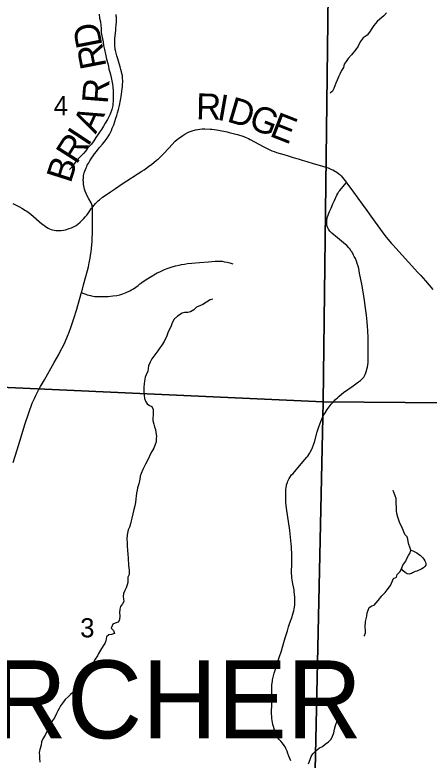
# Model space of a CAD drawing. Extents: x 0 to 34, y 0 to 22.
# Drawn here: x 14.795 to 15.701, y 15.132 to 16.764 of the extents above; entities that cross this region are included whole.
import ezdxf

# ---------------------------------------------------------------- set-up
doc = ezdxf.new("R2010")
doc.units = 0
for name, color, linetype in [('GM_X_Corporation', 7, 'Continuous'), ('GM_X_County_Road', 7, 'Continuous'), ('GM_X_County_Road_Text', 7, 'Continuous'), ('GM_X_Minor_River', 7, 'Continuous'), ('GM_X_Section_Text', 7, 'Continuous'), ('GM_X_Township_Road', 7, 'Continuous'), ('GM_X_Township_Text', 7, 'Continuous')]:
    doc.layers.add(name, color=color, linetype=linetype)

msp = doc.modelspace()

# ---------------------------------------------------------------- linework, layer by layer
at = {"layer": 'GM_X_Corporation'}
for points in [[(14.4709, 16.9847), (15.4816, 16.9282), (15.4691, 15.9163), (14.4583, 15.9623)], [(15.4816, 16.9282), (16.466, 16.9214), (16.4563, 15.9084), (15.4691, 15.9163)], [(14.4583, 15.9623), (15.4691, 15.9163), (15.4475, 14.9085), (14.443, 14.9501)], [(15.4691, 15.9163), (16.4563, 15.9084), (16.441, 14.8856), (15.4475, 14.9085)]]:
    msp.add_lwpolyline(points, close=True, dxfattribs=at)
at = {"layer": 'GM_X_County_Road'}
for points in [[(14.9643, 16.3423), (14.964, 16.3442), (14.9635, 16.3464), (14.9629, 16.3487), (14.9622, 16.3506), (14.9615, 16.3522), (14.9565, 16.361), (14.9523, 16.3687), (14.9504, 16.3728), (14.9484, 16.3776), (14.9468, 16.3825), (14.9461, 16.3855), (14.9454, 16.3896), (14.9449, 16.393), (14.9447, 16.3954), (14.9446, 16.3986), (14.9445, 16.401), (14.9446, 16.4074), (14.9451, 16.4116), (14.9457, 16.4148), (14.9465, 16.418), (14.9478, 16.4218), (14.949, 16.4252), (14.9505, 16.4288), (14.9519, 16.4318), (14.9532, 16.4344), (14.9546, 16.4368), (14.9563, 16.4399), (14.9587, 16.4439), (14.9627, 16.4501), (14.966, 16.4548), (14.9691, 16.4592), (14.973, 16.4645), (14.9769, 16.4695), (14.9808, 16.4743), (14.9862, 16.4804), (14.9925, 16.4883), (14.9964, 16.4937), (15, 16.4993), (15.0016, 16.5019), (15.0033, 16.5048), (15.0047, 16.5078), (15.006, 16.5106), (15.008, 16.5154), (15.011, 16.5229), (15.0134, 16.5301), (15.0158, 16.5379), (15.0177, 16.5437), (15.0192, 16.5491), (15.0213, 16.5568), (15.0235, 16.565), (15.0245, 16.569), (15.0255, 16.5737), (15.0267, 16.5803), (15.0274, 16.5848), (15.0281, 16.5899), (15.0289, 16.5961), (15.0295, 16.6015), (15.03, 16.6067), (15.0303, 16.6098), (15.0305, 16.6126), (15.0307, 16.6159), (15.0308, 16.6195), (15.0305, 16.6249), (15.0302, 16.628), (15.0299, 16.6305), (15.029, 16.6354), (15.0281, 16.6393), (15.0269, 16.6441), (15.0253, 16.6498), (15.0201, 16.6673), (15.0179, 16.6743), (15.0154, 16.6827), (15.0148, 16.6857), (15.0143, 16.688), (15.014, 16.6903), (15.0135, 16.695), (15.0133, 16.6977), (15.0132, 16.7), (15.0132, 16.7028), (15.0133, 16.7069), (15.0136, 16.7117), (15.0154, 16.7301), (15.0158, 16.7349), (15.0163, 16.7422), (15.0168, 16.7483), (15.017, 16.7537), (15.017, 16.7577), (15.0169, 16.7593), (15.0167, 16.7605), (15.0166, 16.7617), (15.0161, 16.7642)], [(14.9643, 16.3423), (14.9654, 16.3437), (14.9685, 16.3474), (14.9712, 16.3504), (14.9771, 16.3563), (14.9798, 16.3589), (14.9865, 16.3644), (14.9899, 16.367), (15.0037, 16.3765), (15.0147, 16.3838), (15.0296, 16.3936), (15.0726, 16.4214), (15.0776, 16.4247), (15.09, 16.4336), (15.0939, 16.4365), (15.105, 16.4456), (15.1089, 16.4489), (15.1142, 16.4538), (15.1202, 16.4597), (15.1319, 16.4719), (15.1458, 16.487), (15.1496, 16.4907), (15.1537, 16.4939), (15.1569, 16.4962), (15.1621, 16.4998), (15.1665, 16.5024), (15.1716, 16.5052), (15.1765, 16.5075), (15.1828, 16.5099), (15.1898, 16.5118), (15.1949, 16.5129), (15.1992, 16.5135), (15.2045, 16.5139), (15.2107, 16.5141), (15.2222, 16.5137), (15.226, 16.5133), (15.2359, 16.5119), (15.2407, 16.5111), (15.2592, 16.5075), (15.2639, 16.5064), (15.2783, 16.5027), (15.2821, 16.5016), (15.2957, 16.4973), (15.299, 16.496), (15.3061, 16.4929), (15.3096, 16.4912), (15.3188, 16.486), (15.3379, 16.4753), (15.3423, 16.473), (15.3541, 16.4675), (15.3573, 16.4662), (15.362, 16.4645), (15.3674, 16.4627), (15.3835, 16.4577), (15.3926, 16.4549), (15.4041, 16.4514), (15.4092, 16.4499), (15.415, 16.4482), (15.4235, 16.4457), (15.434, 16.4427), (15.4479, 16.4387), (15.4657, 16.4334), (15.4773, 16.4297), (15.4804, 16.4286), (15.488, 16.4255), (15.4907, 16.4242), (15.4965, 16.4209), (15.499, 16.4193), (15.5041, 16.4154), (15.5057, 16.4139), (15.5086, 16.4111), (15.5115, 16.4079), (15.5178, 16.4003), (15.5202, 16.3971), (15.5214, 16.3954), (15.5355, 16.3755), (15.5452, 16.3623), (15.5549, 16.3492), (15.5649, 16.3353), (15.574, 16.3228), (15.6045, 16.281), (15.6076, 16.277), (15.6191, 16.263), (15.6217, 16.2601), (15.6768, 16.1999), (15.6831, 16.1928), (15.6934, 16.1811), (15.7011, 16.1723), (15.7095, 16.1624)], [(14.7901, 16.3504), (14.8045, 16.3432), (14.8096, 16.3405), (14.8181, 16.3357), (14.8208, 16.334), (14.8264, 16.3299), (14.8295, 16.3274), (14.8537, 16.3066), (14.857, 16.304), (14.8607, 16.3012), (14.8641, 16.2989), (14.8676, 16.2969), (14.8707, 16.2954), (14.8738, 16.2942), (14.8767, 16.2932), (14.8804, 16.2923), (14.8843, 16.2917), (14.8878, 16.2914), (14.892, 16.2913), (14.8959, 16.2916), (14.9008, 16.2922), (14.9056, 16.2934), (14.9135, 16.2957), (14.9183, 16.2974), (14.9218, 16.2989), (14.9256, 16.3008), (14.9286, 16.3027), (14.9325, 16.3057), (14.9375, 16.3099), (14.9401, 16.3123), (14.9458, 16.3181), (14.9489, 16.3216), (14.9519, 16.3252), (14.9557, 16.3304), (14.9626, 16.3402), (14.9643, 16.3423)]]:
    msp.add_lwpolyline(points, dxfattribs=at)
at = {"layer": 'GM_X_Minor_River'}
for points in [[(14.979, 16.7655), (14.9802, 16.7568), (14.9819, 16.7484), (14.9828, 16.7412), (14.9833, 16.734), (14.9838, 16.7249), (14.9847, 16.7181), (14.9863, 16.7113), (14.9876, 16.7048), (14.9888, 16.6965), (14.9909, 16.6878), (14.9933, 16.6776), (14.9954, 16.667), (14.9979, 16.6572), (14.9995, 16.6507), (15.0007, 16.645), (15.0023, 16.6386), (15.004, 16.6329), (15.0056, 16.6269), (15.0081, 16.6117), (15.009, 16.6061), (15.0095, 16.5966), (15.01, 16.5886), (15.0098, 16.5787), (15.0089, 16.565), (15.0071, 16.5567), (15.0035, 16.5463), (14.9977, 16.5348), (14.9921, 16.5264), (14.9884, 16.5199), (14.984, 16.5129), (14.9796, 16.5068), (14.9755, 16.5006), (14.9718, 16.4949), (14.9674, 16.4876), (14.9626, 16.481), (14.9536, 16.4718), (14.9503, 16.466), (14.9447, 16.4602), (14.938, 16.454), (14.9302, 16.4459), (14.9261, 16.4401), (14.9187, 16.4298), (14.9146, 16.4252)], [(15.6081, 16.768), (15.6025, 16.7619), (15.5936, 16.7545), (15.588, 16.7491), (15.5801, 16.7406), (15.5757, 16.734), (15.5705, 16.7256), (15.5657, 16.7194)], [(15.5657, 16.7194), (15.5571, 16.7132), (15.5504, 16.7044), (15.546, 16.6955), (15.5409, 16.6882), (15.5312, 16.6763), (15.5241, 16.6682), (15.5197, 16.6613), (15.5156, 16.6555), (15.5139, 16.6483), (15.5098, 16.6417), (15.5062, 16.6337), (15.5028, 16.6279), (15.4999, 16.6207), (15.497, 16.6142), (15.4927, 16.6027), (15.4897, 16.5969), (15.4849, 16.5925)], [(15.2276, 16.1412), (15.2223, 16.1399), (15.2063, 16.13), (15.201, 16.1276), (15.1924, 16.1236), (15.1865, 16.1177), (15.179, 16.1134), (15.1729, 16.1124), (15.1661, 16.1123), (15.1608, 16.111), (15.1504, 16.1039), (15.1437, 16.0973), (15.139, 16.0896), (15.1369, 16.083), (15.1329, 16.075), (15.13, 16.0696), (15.1265, 16.0592), (15.1236, 16.0538), (15.1218, 16.0485), (15.1167, 16.0408), (15.1123, 16.0346), (15.1076, 16.0284), (15.1032, 16.0222), (15.0987, 16.0167), (15.0947, 16.0106), (15.0907, 16.0032), (15.0872, 15.9952), (15.0862, 15.9898), (15.0856, 15.9837), (15.0823, 15.9757), (15.0798, 15.9703), (15.0782, 15.9615), (15.0779, 15.9562), (15.0773, 15.949), (15.0771, 15.9436), (15.0769, 15.9376), (15.0774, 15.9311), (15.0787, 15.9239), (15.0808, 15.9183), (15.084, 15.9119), (15.0894, 15.9082), (15.0947, 15.9065), (15.0972, 15.9001), (15.0977, 15.8944), (15.0971, 15.8875), (15.0965, 15.8818), (15.0967, 15.8754), (15.0991, 15.8678), (15.1004, 15.8618), (15.1025, 15.8557), (15.1034, 15.8497), (15.1044, 15.8417), (15.1041, 15.8357), (15.1036, 15.8288), (15.1014, 15.8234), (15.099, 15.815), (15.0942, 15.8077), (15.091, 15.8015), (15.087, 15.7923), (15.0809, 15.78), (15.0751, 15.7681), (15.0708, 15.76), (15.0691, 15.7535), (15.0685, 15.747), (15.0661, 15.737), (15.0633, 15.7286), (15.0622, 15.7233), (15.0609, 15.7168), (15.0603, 15.7099), (15.0597, 15.7042), (15.0584, 15.6962), (15.0571, 15.6886), (15.055, 15.6805), (15.0529, 15.6717), (15.0509, 15.6618), (15.0492, 15.6561), (15.0478, 15.6492), (15.0453, 15.6423), (15.0425, 15.6362), (15.0405, 15.6255), (15.04, 15.6159), (15.0405, 15.6084), (15.0407, 15.6015), (15.0413, 15.5913), (15.0419, 15.5833), (15.0429, 15.5742), (15.0433, 15.5583), (15.0447, 15.5481), (15.0446, 15.5385), (15.0417, 15.5324), (15.042, 15.521), (15.0402, 15.5156), (15.0385, 15.5095), (15.0352, 15.5034), (15.0324, 15.4972), (15.0314, 15.4903), (15.0327, 15.4851), (15.0332, 15.4797), (15.0303, 15.474), (15.0259, 15.4682), (15.0245, 15.4628)], [(15.5597, 15.4037), (15.5598, 15.4048), (15.5619, 15.4105), (15.5618, 15.4162), (15.5612, 15.4234), (15.5624, 15.4356), (15.5651, 15.4475), (15.5657, 15.4547), (15.5704, 15.4662), (15.5756, 15.4698), (15.5808, 15.4714), (15.5897, 15.4819), (15.5978, 15.492), (15.6052, 15.499), (15.6092, 15.5048), (15.6166, 15.5141), (15.6237, 15.5299), (15.6301, 15.5327), (15.6311, 15.5388), (15.6374, 15.5446), (15.6407, 15.5508), (15.6435, 15.5592), (15.6501, 15.5678), (15.6526, 15.5735), (15.6562, 15.5801), (15.6599, 15.5859), (15.6616, 15.592), (15.6588, 15.598), (15.6571, 15.6044), (15.6555, 15.6105), (15.6546, 15.6158), (15.6533, 15.621), (15.6482, 15.6262), (15.6458, 15.6319), (15.6433, 15.639), (15.6398, 15.6458), (15.6373, 15.651), (15.6349, 15.6574), (15.6332, 15.6642), (15.6307, 15.6722), (15.6298, 15.6778), (15.6297, 15.6847), (15.629, 15.6957), (15.6291, 15.7048), (15.6271, 15.7104), (15.6247, 15.7165), (15.6223, 15.7221), (15.6222, 15.7218)], [(15.0245, 15.4628), (15.024, 15.4548), (15.0241, 15.4487), (15.0236, 15.4396), (15.0207, 15.4342), (15.0143, 15.4322), (15.009, 15.4297), (15.0051, 15.4213), (15.0105, 15.4157), (15.0126, 15.4097), (15.0062, 15.4073), (15.0005, 15.4063), (14.9953, 15.402), (14.994, 15.3933), (14.9919, 15.3875), (14.9879, 15.3821), (14.9824, 15.3728), (14.978, 15.3655), (14.9755, 15.3601), (14.9704, 15.3528), (14.9653, 15.3439), (14.9628, 15.3385), (14.9566, 15.3296), (14.9548, 15.3235), (14.9464, 15.3107), (14.9342, 15.2987), (14.9269, 15.2886), (14.9214, 15.2801), (14.9162, 15.2758), (14.911, 15.2707), (14.9047, 15.2645), (14.8992, 15.2567), (14.8948, 15.2509), (14.8916, 15.2455), (14.889, 15.2398), (14.8861, 15.2344), (14.8811, 15.2247), (14.877, 15.2189), (14.8723, 15.2108), (14.8694, 15.2051), (14.864, 15.1935), (14.8612, 15.187), (14.8561, 15.1789), (14.8532, 15.1724), (14.8519, 15.1647), (14.8495, 15.1552), (14.8481, 15.149), (14.8483, 15.1418), (14.8488, 15.1361), (14.849, 15.1278)], [(15.4375, 15.1243), (15.4411, 15.1335), (15.4432, 15.1404), (15.4465, 15.1462), (15.4542, 15.1532), (15.4617, 15.1587), (15.4677, 15.1623), (15.474, 15.1674), (15.4814, 15.1725), (15.4866, 15.1783), (15.4902, 15.1849), (15.4931, 15.1918), (15.4944, 15.1998), (15.4961, 15.2078), (15.5, 15.2178), (15.5025, 15.2255), (15.5061, 15.2355)]]:
    msp.add_lwpolyline(points, dxfattribs=at)
msp.add_spline([(15.6616, 15.592), (15.6784, 15.5833), (15.6898, 15.5718), (15.6939, 15.5593), (15.6809, 15.5487), (15.6679, 15.5434), (15.6576, 15.5393), (15.6407, 15.5508)], degree=3, dxfattribs=at)
at = {"layer": 'GM_X_Township_Road'}
for points in [[(15.3986, 15.1308), (15.3967, 15.1354), (15.3942, 15.1408), (15.3921, 15.1468), (15.3905, 15.1517), (15.3881, 15.1575), (15.3861, 15.1612), (15.3839, 15.1644), (15.3802, 15.1692), (15.3766, 15.1733), (15.3731, 15.1773), (15.3705, 15.181), (15.3688, 15.1839), (15.3668, 15.1878), (15.3652, 15.1914), (15.3636, 15.1955), (15.3619, 15.2007), (15.3605, 15.2054), (15.3592, 15.2104), (15.3584, 15.2142), (15.3576, 15.2191), (15.3572, 15.2234), (15.357, 15.2261), (15.3566, 15.2349), (15.3568, 15.2559), (15.3569, 15.2645), (15.3571, 15.2928), (15.3574, 15.2969), (15.3583, 15.3047), (15.3589, 15.3081), (15.3616, 15.3198), (15.3624, 15.3227), (15.3688, 15.3427), (15.3735, 15.357), (15.3781, 15.3717), (15.3806, 15.3797), (15.3866, 15.4), (15.3891, 15.4084), (15.3911, 15.4151), (15.3937, 15.4236), (15.3968, 15.4329), (15.4013, 15.4461), (15.4025, 15.4496), (15.405, 15.4591), (15.4059, 15.4631), (15.4072, 15.4712), (15.4075, 15.4745), (15.4078, 15.4815), (15.4077, 15.4859), (15.4076, 15.4888), (15.4063, 15.5013), (15.4058, 15.5046), (15.4034, 15.518), (15.4012, 15.5315), (15.4008, 15.5342), (15.4002, 15.5424), (15.4009, 15.5636), (15.401, 15.5669), (15.401, 15.5812), (15.3999, 15.5994), (15.3994, 15.6055), (15.3973, 15.6272), (15.3965, 15.6345), (15.3935, 15.6542), (15.3896, 15.6788), (15.3891, 15.6834), (15.3879, 15.6969), (15.3876, 15.7015), (15.3875, 15.7104), (15.3876, 15.7144), (15.3881, 15.7245), (15.3886, 15.7292), (15.3891, 15.7327), (15.3895, 15.7347), (15.3911, 15.74), (15.3923, 15.7429), (15.3937, 15.746), (15.3953, 15.7489), (15.3964, 15.7506), (15.4005, 15.7564), (15.4035, 15.76), (15.4214, 15.781), (15.4335, 15.7952), (15.4356, 15.7979), (15.4396, 15.8035), (15.4411, 15.8062), (15.4443, 15.8126), (15.4452, 15.8147), (15.4488, 15.8243), (15.4503, 15.8286), (15.4564, 15.8507), (15.4597, 15.8618), (15.4618, 15.8678), (15.464, 15.8736), (15.4662, 15.8786), (15.468, 15.8825), (15.4705, 15.8873), (15.4728, 15.8913), (15.4783, 15.8998), (15.4806, 15.9029), (15.4872, 15.9113), (15.4912, 15.9159), (15.4964, 15.9214), (15.5012, 15.9261), (15.5036, 15.9283), (15.5097, 15.9335), (15.5138, 15.9367), (15.5349, 15.9519), (15.5471, 15.9606), (15.5509, 15.9634), (15.5541, 15.9661), (15.5558, 15.9679), (15.5581, 15.9707), (15.5599, 15.9735), (15.5615, 15.9764), (15.563, 15.9801), (15.5638, 15.9823), (15.5658, 15.9899), (15.5663, 15.9927), (15.5676, 16.0025), (15.5678, 16.005), (15.5683, 16.0171), (15.5678, 16.0556), (15.5673, 16.0731), (15.5668, 16.081), (15.5659, 16.0919), (15.5643, 16.1066), (15.5623, 16.1219), (15.5599, 16.1387), (15.5567, 16.1573), (15.5539, 16.1739), (15.5491, 16.1981), (15.5472, 16.2082), (15.546, 16.2136), (15.5441, 16.2193), (15.5421, 16.2247), (15.5399, 16.23), (15.5376, 16.235), (15.5362, 16.2378), (15.5327, 16.244), (15.531, 16.2466), (15.5275, 16.2512), (15.5258, 16.2534), (15.521, 16.2585), (15.5185, 16.261), (15.5049, 16.2721), (15.4967, 16.2789), (15.4925, 16.2823), (15.4884, 16.2858), (15.4838, 16.2904), (15.4808, 16.2948), (15.4789, 16.2988), (15.4778, 16.3027), (15.4775, 16.3055), (15.4777, 16.309), (15.4778, 16.3134), (15.4785, 16.3187), (15.4792, 16.3216), (15.4803, 16.3252), (15.4817, 16.3293), (15.4833, 16.3335), (15.4868, 16.3408), (15.4907, 16.3497), (15.494, 16.3571), (15.4993, 16.369), (15.5013, 16.3727), (15.5037, 16.377), (15.5056, 16.3795), (15.5085, 16.3831), (15.5202, 16.3971)], [(14.8593, 15.965), (14.8804, 16.0023), (14.8907, 16.0204), (14.8947, 16.028), (14.901, 16.04), (14.9046, 16.0477), (14.9098, 16.0601), (14.9133, 16.0691), (14.917, 16.0794), (14.9207, 16.09), (14.9238, 16.0993), (14.93, 16.1192), (14.9395, 16.1534), (14.9403, 16.1561), (14.9424, 16.1635), (14.945, 16.1729), (14.9501, 16.1912), (14.9534, 16.2039), (14.9555, 16.212), (14.9574, 16.2205), (14.9595, 16.2309), (14.9605, 16.238), (14.9615, 16.245), (14.9625, 16.2522), (14.9632, 16.2601), (14.9636, 16.2667), (14.964, 16.2756), (14.9644, 16.2854), (14.9645, 16.2967), (14.9648, 16.3071), (14.9649, 16.3173), (14.9648, 16.3344), (14.9645, 16.3396), (14.9643, 16.3423)], [(14.9403, 16.1561), (14.9434, 16.1547), (14.9501, 16.152), (14.9527, 16.1511), (14.9604, 16.1491), (14.9627, 16.1485), (14.966, 16.1479), (14.9695, 16.1475), (14.9737, 16.1473), (14.9986, 16.1475), (15.0091, 16.1483), (15.0178, 16.1495), (15.0246, 16.1508), (15.0312, 16.1528), (15.0386, 16.1556), (15.0466, 16.1594), (15.0503, 16.1618), (15.0543, 16.164), (15.0591, 16.1677), (15.0642, 16.1714), (15.0682, 16.1748), (15.0726, 16.178), (15.0758, 16.1801), (15.0856, 16.1862), (15.0932, 16.1909), (15.1025, 16.1966), (15.1062, 16.1987), (15.1116, 16.2013), (15.1165, 16.2035), (15.1221, 16.206), (15.1304, 16.2092), (15.1392, 16.212), (15.1461, 16.214), (15.1543, 16.2161), (15.1596, 16.2172), (15.1657, 16.2182), (15.1725, 16.2191), (15.1818, 16.2202), (15.1986, 16.2216), (15.2185, 16.2234), (15.233, 16.2245), (15.2378, 16.2247), (15.2433, 16.2245), (15.2481, 16.2242), (15.2536, 16.2234), (15.2595, 16.2222), (15.2649, 16.221), (15.272, 16.2188)], [(14.7906, 15.784), (14.7996, 15.8116), (14.8082, 15.8397), (14.8167, 15.8672), (14.8249, 15.8925), (14.8272, 15.899), (14.8302, 15.9072), (14.8327, 15.9134), (14.8373, 15.9238), (14.8396, 15.9287), (14.8482, 15.9452), (14.851, 15.9503), (14.8593, 15.965)]]:
    msp.add_lwpolyline(points, dxfattribs=at)

# ---------------------------------------------------------------- texts
at = {"layer": 'GM_X_County_Road_Text'}
for s, rotation, p in [('D', 100.9924, (14.9866, 16.6968)), ('R', 100.964, (14.9955, 16.651)), ('R', 85.5326, (14.998, 16.5678)), ('R', 359.0281, (15.191, 16.5351)), ('I', 350.0359, (15.2354, 16.5345)), ('D', 343.5767, (15.2567, 16.5309)), ('G', 338.8108, (15.3035, 16.5172)), ('A', 65.2674, (14.9716, 16.5013)), ('E', 338.5782, (15.35, 16.4991)), ('I', 56.6325, (14.9542, 16.4736)), ('R', 57.5126, (14.9292, 16.4345)), ('B', 72.3007, (14.9167, 16.3935))]:
    msp.add_text(s, height=0.0568, rotation=rotation, dxfattribs=at).set_placement(p)
at = {"layer": 'GM_X_Section_Text'}
for s, p in [('4', (14.8798, 16.5441)), ('3', (14.9377, 15.4009))]:
    msp.add_text(s, height=0.0419, rotation=0, dxfattribs=at).set_placement(p)
at = {"layer": 'GM_X_Township_Text'}
msp.add_text('ARCHER', height=0.17045, rotation=0, dxfattribs=at).set_placement((14.5919, 15.1799))

doc.saveas('drawing.dxf')
